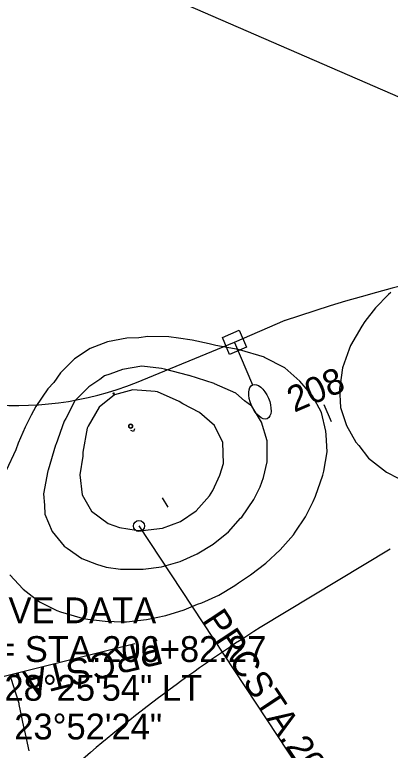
# Model space of a CAD drawing. Extents: x 1598538 to 1602183, y 285823 to 288192.
# Drawn here: x 1601091 to 1601192.8, y 286669.9 to 286869.3 of the extents above; entities that cross this region are included whole.
import ezdxf

# ---------------------------------------------------------------- set-up
doc = ezdxf.new("R2010")
doc.units = 0
for name, color, linetype in [('CM_Corridor_Conceptual', 7, 'Continuous'), ('Default', 7, 'Continuous'), ('MD_P_ACSC_B', 7, 'Continuous'), ('MD_P_AGB_B', 7, 'Continuous'), ('PV_P_Curb', 7, 'Continuous'), ('RW_P_Esmt_LA', 7, 'Continuous'), ('RW_P_Esmt_TMP', 7, 'Continuous')]:
    doc.layers.add(name, color=color, linetype=linetype)

msp = doc.modelspace()

# ---------------------------------------------------------------- linework, layer by layer
at = {"layer": 'Default'}
for points in [[(1601192.92, 286794.02), (1601192.3, 286793.4), (1601188.8, 286789.83), (1601185.92, 286786.15), (1601185.05, 286784.83), (1601182.05, 286779.61), (1601181.67, 286778.58), (1601179.8, 286773.58), (1601179.17, 286768.99), (1601179.05, 286768.05), (1601179.3, 286762.77), (1601180.92, 286757.93), (1601183.42, 286753.4), (1601184.3, 286752.52), (1601186.92, 286749.08), (1601191.8, 286745.3), (1601191.8, 286745.27), (1601198.05, 286742.05)], [(1601089.67, 286717.46), (1601093.3, 286713.55), (1601094.05, 286712.96), (1601097.67, 286710.11), (1601102.42, 286707.8), (1601103.42, 286707.4), (1601109.3, 286705.74), (1601110.8, 286705.46), (1601115.55, 286704.86), (1601120.42, 286704.74), (1601121.3, 286704.74), (1601126.67, 286705.36), (1601131.92, 286706.43), (1601136.92, 286707.96), (1601140.55, 286709.46), (1601141.67, 286709.86), (1601146.3, 286711.96), (1601150.67, 286714.58), (1601151.67, 286715.24), (1601154.92, 286717.4), (1601159.05, 286720.58), (1601162.92, 286724.21), (1601166.55, 286728.3), (1601167.05, 286728.99), (1601169.8, 286733.15), (1601171.92, 286737.33), (1601172.55, 286738.77), (1601174.55, 286744.46), (1601174.8, 286745.55), (1601175.67, 286750.77), (1601175.42, 286755.4), (1601175.3, 286756.36), (1601174.17, 286761.49), (1601171.67, 286765.96), (1601168.3, 286769.96), (1601167.42, 286770.68), (1601164.17, 286773.58), (1601158.67, 286776.4), (1601158.67, 286776.43), (1601151.92, 286778.43), (1601151.55, 286778.49), (1601145.55, 286779.58), (1601143.67, 286780.08), (1601139.05, 286781.08), (1601135.42, 286781.58), (1601132.8, 286781.93), (1601127.05, 286782.02), (1601124.67, 286781.71), (1601121.42, 286781.61), (1601116.17, 286780.65), (1601111.42, 286778.8), (1601107.17, 286775.96), (1601103.42, 286772.21), (1601101.55, 286769.61), (1601099.92, 286767.86), (1601096.67, 286763.05), (1601095.42, 286760.71), (1601093.8, 286757.49), (1601091.92, 286753.15), (1601091.3, 286751.3), (1601088.67, 286745.71)], [(1601117.67, 286766.68), (1601117.8, 286766.46), (1601117.8, 286766.46), (1601117.67, 286766.68), (1601117.67, 286766.68)], [(1601117.8, 286766.46), (1601117.92, 286766.55), (1601117.92, 286766.55), (1601117.8, 286766.46), (1601117.8, 286766.46)], [(1601122.17, 286758.21), (1601121.92, 286758.02), (1601121.92, 286758.02), (1601122.17, 286758.21), (1601122.17, 286758.21)], [(1601122.67, 286758.21), (1601122.42, 286758.27), (1601122.42, 286758.27), (1601122.67, 286758.21), (1601122.67, 286758.21)], [(1601122.92, 286757.99), (1601122.67, 286758.21), (1601122.67, 286758.21), (1601122.92, 286757.99), (1601122.92, 286757.99)], [(1601122.67, 286757.27), (1601122.92, 286757.46), (1601122.92, 286757.46), (1601122.67, 286757.27), (1601122.67, 286757.27)], [(1601123.42, 286757.05), (1601123.17, 286756.33), (1601122.42, 286756.55)], [(1601094.92, 286669.74), (1601093.92, 286674.33), (1601093.42, 286676.24), (1601092.17, 286682.3), (1601092.17, 286682.58), (1601090.05, 286689.33)]]:
    msp.add_lwpolyline(points, dxfattribs=at)
for points in [[(1601104.42, 286725.18), (1601105.17, 286724.68), (1601109.17, 286721.86), (1601113.17, 286720.3), (1601115.8, 286719.55), (1601119.67, 286718.96), (1601125.42, 286718.99), (1601125.8, 286719.02), (1601130.8, 286719.65), (1601135.8, 286721.05), (1601140.42, 286723.15), (1601144.8, 286725.77), (1601148.92, 286729.08), (1601152.17, 286732.8), (1601152.55, 286733.11), (1601155.8, 286737.83), (1601157.55, 286741.3), (1601158.42, 286743.86), (1601159.42, 286748.05), (1601159.42, 286752.96), (1601159.42, 286753.8), (1601157.92, 286758.8), (1601155.3, 286763.15), (1601153.3, 286764.61), (1601150.92, 286766.65), (1601145.17, 286769.21), (1601145.05, 286769.3), (1601138.3, 286771.46), (1601138.17, 286771.49), (1601131.55, 286773.24), (1601130.8, 286773.4), (1601125.42, 286774.02), (1601120.17, 286773.15), (1601116.8, 286771.86), (1601115.3, 286771.36), (1601114.05, 286770.4), (1601111.05, 286768.43), (1601107.3, 286764.58), (1601104.8, 286759.83), (1601104.42, 286759.08), (1601102.17, 286752.68), (1601102.05, 286752.61), (1601100.05, 286745.83), (1601099.92, 286745.61), (1601098.8, 286739.43), (1601099.05, 286736.3), (1601099.17, 286733.9), (1601101.17, 286729.21)], [(1601116.3, 286731.33), (1601119.42, 286730.3), (1601123.92, 286729.58), (1601125.67, 286729.46), (1601131.05, 286730.05), (1601135.92, 286731.9), (1601140.17, 286734.77), (1601143.8, 286738.9), (1601144.67, 286740.33), (1601146.55, 286744.46), (1601147.55, 286747.61), (1601147.42, 286753.3), (1601145.17, 286757.9), (1601141.05, 286761.49), (1601136.55, 286763.77), (1601135.55, 286764.4), (1601129.67, 286767.02), (1601129.05, 286767.18), (1601123.05, 286767.61), (1601118.05, 286766.24), (1601113.92, 286762.9), (1601110.92, 286757.74), (1601110.67, 286757.18), (1601109.42, 286750.74), (1601109.42, 286749.61), (1601108.67, 286744.58), (1601109.3, 286739.15), (1601111.8, 286734.71)], [(1601117.8, 286766.77), (1601117.67, 286766.68), (1601117.8, 286766.46), (1601117.92, 286766.55)], [(1601117.8, 286766.77), (1601117.67, 286766.68), (1601117.8, 286766.46), (1601117.92, 286766.55)], [(1601117.8, 286766.77), (1601117.67, 286766.68), (1601117.67, 286766.68), (1601117.8, 286766.77)], [(1601117.92, 286766.55), (1601117.8, 286766.77), (1601117.8, 286766.77), (1601117.92, 286766.55)], [(1601122.67, 286758.21), (1601122.42, 286758.27), (1601122.17, 286758.21), (1601121.92, 286758.02), (1601121.92, 286757.77), (1601121.92, 286757.49), (1601122.17, 286757.3), (1601122.42, 286757.21), (1601122.67, 286757.27), (1601122.92, 286757.46), (1601122.92, 286757.74), (1601122.92, 286757.99)], [(1601122.67, 286758.21), (1601122.42, 286758.27), (1601122.17, 286758.21), (1601121.92, 286758.02), (1601121.92, 286757.77), (1601121.92, 286757.49), (1601122.17, 286757.3), (1601122.42, 286757.21), (1601122.67, 286757.27), (1601122.92, 286757.46), (1601122.92, 286757.74), (1601122.92, 286757.99)], [(1601121.92, 286758.02), (1601121.92, 286757.77), (1601121.92, 286757.77), (1601121.92, 286758.02)], [(1601121.92, 286757.77), (1601121.92, 286757.49), (1601121.92, 286757.49), (1601121.92, 286757.77)], [(1601121.92, 286757.49), (1601122.17, 286757.3), (1601122.17, 286757.3), (1601121.92, 286757.49)], [(1601122.42, 286758.27), (1601122.17, 286758.21), (1601122.17, 286758.21), (1601122.42, 286758.27)], [(1601122.17, 286757.3), (1601122.42, 286757.21), (1601122.42, 286757.21), (1601122.17, 286757.3)], [(1601122.42, 286757.21), (1601122.67, 286757.27), (1601122.67, 286757.27), (1601122.42, 286757.21)], [(1601122.92, 286757.74), (1601122.92, 286757.99), (1601122.92, 286757.99), (1601122.92, 286757.74)], [(1601122.92, 286757.46), (1601122.92, 286757.74), (1601122.92, 286757.74), (1601122.92, 286757.46)]]:
    msp.add_lwpolyline(points, close=True, dxfattribs=at)
at = {"layer": 'MD_P_ACSC_B'}
msp.add_line((1600591.71, 287110.09), (1601244.34, 286825.47), dxfattribs=at)
at = {"layer": 'MD_P_AGB_B'}
for p, q in [((1601176.89, 286758.93), (1601174.9, 286763.52)), ((1601132.62, 286735.78), (1601131.04, 286738.33))]:
    msp.add_line(p, q, dxfattribs=at)
at = {"layer": 'PV_P_Curb'}
for p, q in [((1601124.67, 286730.7), (1601186.62, 286636.79)), ((1601014.4, 286671.56), (1601123.55, 286698.81))]:
    msp.add_line(p, q, dxfattribs=at)
msp.add_circle((1601124.67, 286730.7), 1.5, dxfattribs=at)
at = {"layer": 'RW_P_Esmt_LA'}
msp.add_line((1601150.56, 286780.45), (1601155.48, 286768.96), dxfattribs=at)
msp.add_lwpolyline([(1601151.87, 286783.74), (1601153.84, 286779.14), (1601149.24, 286777.17), (1601147.27, 286781.77)], close=True, dxfattribs=at)
msp.add_ellipse((1601157.45, 286764.37), major_axis=(1.97, -4.6), ratio=0.5, dxfattribs=at)
at = {"layer": 'RW_P_Esmt_TMP'}
for p, q in [((1601150.54, 286780.5), (1601164.31, 286786.44)), ((1601123.98, 286769.56), (1601150.54, 286780.5)), ((1601192.79, 286724.4), (1601157.48, 286703.15))]:
    msp.add_line(p, q, dxfattribs=at)
for centre, radius, start, end in [((1601309.46, 286355.9), 454.33, 73.5556, 108.674), ((1601091.42, 286851.54), 88.2, 235.1857, 291.6614), ((1601373.64, 286361.68), 404.14, 122.3345, 131.265)]:
    msp.add_arc(centre, radius, start, end, dxfattribs=at)

# ---------------------------------------------------------------- texts
at = {"layer": 'CM_Corridor_Conceptual'}
for s, p in [('CURVE DATA', (1601069.01, 286704.32)), ('P.I. = STA. ', (1601069.01, 286693.82)), ('206+82.27', (1601114.68, 286693.82)), ('28°25\'54" LT', (1601088.2, 286683.32)), ('23°52\'24"', (1601090.86, 286672.82))]:
    msp.add_text(s, height=7, dxfattribs=at).set_placement(p)
at = {"layer": 'MD_P_AGB_B'}
msp.add_text('208', height=7, rotation=23.393, dxfattribs=at).set_placement((1601166.75, 286761.36))
at = {"layer": 'PV_P_Curb'}
for s, rotation, p in [('PRC', 303.4087, (1601141.64, 286705.17)), ('PRC', 194.0171, (1601129.95, 286700.3)), (' STA. ', 194.0171, (1601113.12, 286696.1)), (' STA. ', 303.4087, (1601151.19, 286690.68)), ('207+40.57', 303.4087, (1601164.2, 286670.96))]:
    msp.add_text(s, height=7, rotation=rotation, dxfattribs=at).set_placement(p)

doc.saveas('drawing.dxf')
